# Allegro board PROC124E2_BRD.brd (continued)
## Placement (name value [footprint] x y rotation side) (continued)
R380  10K  [RES0201_0-5]  62.28 89.56 270 bottom
R381  2.2K  [RES0201_0-5]  61.52 89.56 90 bottom
R382  10K  [RES0201_0-5]  2.36 86.33 0 bottom
R383  0E  [RES0201_0-5]  54.28 88.78 0 bottom
R384  2.2K  [RES0402_0-5]  31.7 88.31 90 bottom
R385  0E  [RES0201_0-5]  64.27 88.3 180 bottom
R386  100K_1%  [RES0402_0-5]  64.42 86.83 270 bottom
R387  56.2K_1%  [RES0402_0-5]  26.64 86.36 90 bottom
R388  10E_1%  [RES0402_0-5]  20.85 85.25 0 bottom
R389  316K_1%  [RES0402_0-5]  64.42 84.8 90 bottom
R390  100K_1%  [RES0402_0-5]  63.15 84.8 270 bottom
R391  10E_1%  [RES0402_0-5]  20.85 83.98 0 bottom
R392  0E  [RES0201_0-5]  15.52 83.75 90 bottom
R393  0E  [RES0201_0-5]  78.14 83.55 0 bottom
R394  0E  [RES0201_0-5]  80.81 83.48 0 bottom
R395  220E  [RES0402_0-5]  82.33 82.87 270 bottom
R396  10E_1%  [RES0402_0-5]  23.79 80.01 180 bottom
R397  0E  [RES0201_0-5]  29.06 79.94 0 bottom
R398  49.9K_1%  [RES0201_0-5]  48.4 79.36 0 bottom
R399  10E_1%  [RES0402_0-5]  23.79 78.74 180 bottom
R400  49.9K_1%  [RES0201_0-5]  51.12 78.6 270 bottom
R401  49.9K_1%  [RES0201_0-5]  49.41 78.27 0 bottom
R402  1K_1%  [RES0201_0-5]  2.63 77.45 0 bottom
R403  0E  [RES0201_0-5]  19.29 76.95 180 bottom
R404  10K  [RES0201_0-5]  11.21 76.91 0 bottom
R405  0E  [RES0201_0-5]  18 76.67 270 bottom
R406  1K_1%  [RES0402_0-5]  8.25 73.89 90 bottom
R407  10K  [RES0201_0-5]  50.84 73.57 180 bottom
R408  10E_1%  [RES0402_0-5]  18.59 72.48 180 bottom
R409  0E  [RES0201_0-5]  24.09 72.34 0 bottom
R410  10E_1%  [RES0402_0-5]  18.59 71.21 180 bottom
R411  100K_1%  [RES0402_0-5]  44.06 71.03 180 bottom
R412  4.7K  [RES0201_0-5]  49.13 70.29 0 bottom
R413  10E_1%  [RES0402_0-5]  7.7 69.9 0 bottom
R414  0E  [RES0201_0-5]  2.44 69.07 90 bottom
R415  10E_1%  [RES0402_0-5]  7.7 68.63 0 bottom
R416  4.7K  [RES0201_0-5]  42.53 66.8 180 bottom
R417  0E  [RES0603_0-75]  79.67 65.19 270 bottom
R418  10K  [RES0201_0-5]  45.07 60.59 0 bottom
R419  4.7K  [RES0201_0-5]  39.99 60.59 180 bottom
R420  0E  [RES0201_0-5]  17.34 59.07 180 bottom
R421  0E  [RES0201_0-5]  15.43 59.07 0 bottom
R422  10K_1%  [RES0201_0-5]  70.2 58.05 180 bottom
R423  10K  [RES0201_0-5]  9 55.79 180 bottom
R424  4.7K  [RES0201_0-5]  7.27 54.32 270 bottom
R425  10K  [RES0201_0-5]  77.1 53.86 270 bottom
R426  10K  [RES0201_0-5]  76.19 53.86 270 bottom
R427  0E  [RES0201_0-5]  73.18 53.4 270 bottom
R428  0E  [RES0201_0-5]  80.43 53.27 270 bottom
R429  0E  [RES0201_0-5]  79.41 53.27 270 bottom
R430  0E  [RES0201_0-5]  71.66 53.26 90 bottom
R431  4.7K  [RES0201_0-5]  8.95 53.23 180 bottom
R432  2.2K  [RES0201_0-5]  19.09 53.18 0 bottom
R433  0E  [RES0201_0-5]  19.1 52.46 0 bottom
R434  0E  [RES0402_0-5]  67.04 51.45 90 bottom
R435  100K_1%  [RES0402_0-5]  16.12 51.45 180 bottom
R436  10K  [RES0201_0-5]  20.98 50.94 270 bottom
R437  1M_1%  [RES0402_0-5]  18.66 50.72 270 bottom
R438  10K  [RES0201_0-5]  24.21 50.54 270 bottom
R439  10K  [RES0201_0-5]  23.29 50.54 270 bottom
R440  100K_1%  [RES0402_0-5]  29.5 49.51 0 bottom
R441  32.4K_1%  [RES0402_0-5]  31.13 48.68 90 bottom
R442  100K  [RES0201_0-5]  32.15 48.51 270 bottom
R443  10K  [RES0201_0-5]  25.5 47.89 180 bottom
R444  1K_1%  [RES0402_0-5]  27.91 47.32 90 bottom
R445  100K_1%  [RES0402_0-5]  29.5 46.85 0 bottom
R446  0E  [RES0201_0-5]  25.5 46.68 180 bottom
R447  0E  [RES0201_0-5]  25.5 45.92 180 bottom
R448  100K_1%  [RES0402_0-5]  13.44 45.8 180 bottom
R449  0E  [RES0201_0-5]  15.22 45.69 180 bottom
R450  43.2K_1%  [RES0402_0-5]  29.5 45.58 180 bottom
R451  10K  [RES0201_0-5]  59.93 44.97 180 bottom
R452  10K_1%  [RES0201_0-5]  15.22 44.93 180 bottom
R453  0E  [RES0402_0-5]  25.81 44.74 0 bottom
R454  100K_1%  [RES0402_0-5]  13.44 44.53 180 bottom
R455  10K  [RES0201_0-5]  61.16 44.41 90 bottom
R456  10K  [RES0201_0-5]  59.93 44.21 0 bottom
R457  0E  [RES0402_0-5]  68.03 43.72 180 bottom
R458  2.2K_1%  [RES0201_0-5]  78.35 43.49 180 bottom
R459  0E  [RES0402_0-5]  25.81 43.47 0 bottom
R460  10K  [RES0201_0-5]  64.02 42.58 90 bottom
R461  0E  [RES0402_0-5]  25.81 42.2 0 bottom
R462  10K  [RES0201_0-5]  49.33 42.09 270 bottom
R463  10K  [RES0201_0-5]  49.62 41.07 180 bottom
R464  0E  [RES0402_0-5]  25.77 40.63 0 bottom
R465  0E  [RES0201_0-5]  21.45 40.04 0 bottom
R466  100K  [RES0201_0-5]  23.2 40.02 270 bottom
R467  0E  [RES0201_0-5]  50.26 39.23 0 bottom
R468  10K  [RES0201_0-5]  51.82 38.95 270 bottom
R469  10K  [RES0201_0-5]  62.11 38.82 90 bottom
R470  10K  [RES0201_0-5]  56.11 38.8 180 bottom
R471  10K  [RES0201_0-5]  57.29 38.04 180 bottom
R472  10K  [RES0201_0-5]  55.23 36.28 90 bottom
R473  4.7K  [RES0201_0-5]  62.71 35.25 270 bottom
R474  4.7K  [RES0201_0-5]  61.75 35.25 270 bottom
R475  1K_1%  [RES0201_0-5]  11.35 35.17 0 bottom
R476  1K_1%  [RES0201_0-5]  10.3 34.3 270 bottom
R477  10K_1%  [RES0201_0-5]  15.04 33.92 90 bottom
R478  100K_1%  [RES0402_0-5]  11.44 33.32 270 bottom
R479  4.7K  [RES0201_0-5]  62.74 33.16 270 bottom
R480  4.7K  [RES0201_0-5]  61.72 33.16 270 bottom
R481  0E  [RES0201_0-5]  22.73 33.02 0 bottom
R482  10K_1%  [RES0201_0-5]  15.01 32.59 270 bottom
R483  10K  [RES0201_0-5]  50.11 28.85 180 bottom
R484  10K_1%  [RES0201_0-5]  17.65 28.36 0 bottom
R485  10K  [RES0201_0-5]  80.53 27.83 90 bottom
R486  30K  [RES0402_0-5]  77.79 27.26 90 bottom
R487  51K  [RES0402_0-5]  76.52 27.26 270 bottom
R488  10K  [RES0201_0-5]  46.96 27.19 0 bottom
R489  10K  [RES0201_0-5]  42.15 27.15 180 bottom
R490  10K  [RES0201_0-5]  70.34 25.68 0 bottom
R491  1.1K_1%  [RES0201_0-5]  80.53 25.5 270 bottom
R492  10K  [RES0201_0-5]  70.34 24.92 180 bottom
R493  100E_1%  [RES0402_0-5]  56.54 24.69 180 bottom
R494  33E  [RES0201_0-5]  47.58 24.36 270 bottom
R495  10K  [RES0201_0-5]  44.46 24.01 90 bottom
R496  10K  [RES0201_0-5]  39.34 23.91 270 bottom
R497  10K  [RES0201_0-5]  66 23.89 90 bottom
R498  0E  [RES0201_0-5]  78.98 23.86 270 bottom
R499  10K  [RES0201_0-5]  14.37 23.81 90 bottom
R500  10K  [RES0201_0-5]  11.96 23.81 90 bottom
R501  10K  [RES0201_0-5]  11.2 23.81 90 bottom
R502  0E  [RES0201_0-5]  62.19 23.66 270 bottom
R503  0E  [RES0201_0-5]  61.43 23.66 270 bottom
R504  10K  [RES0201_0-5]  64.83 23.61 180 bottom
R505  4.7K  [RES0201_0-5]  37.83 23.53 180 bottom
R506  2.2K  [RES0201_0-5]  13.18 23.53 0 bottom
R507  1K_1%  [RES0402_0-5]  72.73 23.44 0 bottom
R508  22E_1%  [RES0201_0-5]  67.71 23.05 180 bottom
R509  10K  [RES0201_0-5]  65.28 22.54 0 bottom
R510  10K  [RES0201_0-5]  32.3 22.36 0 bottom
R511  1K_1%  [RES0402_0-5]  72.73 22.17 0 bottom
R512  100E_1%  [RES0402_0-5]  45.09 22.05 270 bottom
R513  10K  [RES0201_0-5]  32.3 21.47 180 bottom
R514  10K  [RES0201_0-5]  51.07 20.96 270 bottom
R515  1K_1%  [RES0402_0-5]  72.73 20.9 0 bottom
R516  4.7K  [RES0201_0-5]  32.61 20.28 90 bottom
R517  10K  [RES0201_0-5]  45.81 19.76 0 bottom
R518  1K_1%  [RES0402_0-5]  72.73 19.63 0 bottom
R519  4.7K  [RES0201_0-5]  51.38 19.51 0 bottom
R520  10K  [RES0201_0-5]  57.9 19.46 0 bottom
R521  10K  [RES0201_0-5]  45.81 18.84 180 bottom
R522  22E_1%  [RES0201_0-5]  51.35 18.68 180 bottom
R523  10K  [RES0201_0-5]  61.41 18.35 270 bottom
R524  10K  [RES0201_0-5]  59.23 18.35 270 bottom
R525  0E  [RES0201_0-5]  60.4 18.14 270 bottom
R526  0E  [RES0201_0-5]  58.21 18.14 270 bottom
R527  10K  [RES0201_0-5]  39.16 18.09 180 bottom
R528  4.7K  [RES0201_0-5]  24.85 18.02 270 bottom
R529  0E  [RES0201_0-5]  57.07 17.97 270 bottom
R530  10K  [RES0201_0-5]  45.92 17.92 180 bottom
R531  10K  [RES0201_0-5]  42.74 17.55 90 bottom
R532  10K  [RES0201_0-5]  35.88 17.55 90 bottom
R533  10K  [RES0201_0-5]  24.14 17.46 270 bottom
R534  10K  [RES0201_0-5]  23.25 17.46 90 bottom
R535  10K  [RES0201_0-5]  47.66 17.15 180 bottom
R536  0E  [RES0201_0-5]  70.01 17.02 0 bottom
R537  4.7K  [RES0201_0-5]  67.78 16.82 0 bottom
R538  10K  [RES0201_0-5]  31.57 16.7 270 bottom
R539  0E  [RES0805_0-75]  74.45 16.46 270 bottom
R540  0E  [RES0201_0-5]  55.83 16.14 270 bottom
R541  10K  [RES0201_0-5]  64.97 16.1 270 bottom
R542  10K  [RES0201_0-5]  62.78 16.1 270 bottom
R543  10K  [RES0201_0-5]  60.52 16.1 270 bottom
R544  0E  [RES0201_0-5]  54.56 16.02 270 bottom
R545  0E  [RES0201_0-5]  53.29 16.02 270 bottom
R546  0E  [RES0201_0-5]  51.46 16.02 270 bottom
R547  4.7K  [RES0201_0-5]  34.96 15.99 180 bottom
R548  12K_1%  [RES0402_0-5]  16.86 15.94 0 bottom
R549  0E  [RES0201_0-5]  63.95 15.89 270 bottom
R550  0E  [RES0201_0-5]  61.77 15.89 270 bottom
R551  0E  [RES0201_0-5]  59.51 15.89 270 bottom
R552  0E  [RES0201_0-5]  57.25 15.89 270 bottom
R553  0E  [RES0201_0-5]  67.43 15.57 0 bottom
R554  4.7K  [RES0201_0-5]  20.66 15.46 180 bottom
R555  4.7K  [RES0201_0-5]  66 15.29 90 bottom
R556  10K  [RES0201_0-5]  19.47 15.15 270 bottom
R557  10K  [RES0201_0-5]  18.59 15.15 90 bottom
R558  33E  [RES0201_0-5]  39.15 14.39 0 bottom
R559  100K_1%  [RES0402_0-5]  44.75 13.98 90 bottom
R560  10K  [RES0201_0-5]  35.24 11.49 0 bottom
R561  10K  [RES0201_0-5]  31.14 10.28 90 bottom
R562  10K  [RES0201_0-5]  35.24 10.22 0 bottom
R563  0E  [RES0201_0-5]  43.09 9.71 180 bottom
R564  10K  [RES0201_0-5]  32.04 9.43 270 bottom
R565  0E  [RES0402_0-5]  44.82 8.19 90 bottom
R566  4.7K  [RES0201_0-5]  31.81 7.83 90 bottom
R567  10K  [RES0201_0-5]  73.32 149.61 270 bottom
R568  10K  [RES0201_0-5]  72.5 144.94 0 bottom
R569  10K  [RES0201_0-5]  71.61 143.93 180 bottom
R570  10K  [RES0201_0-5]  70.11 142.73 180 bottom
R571  10K  [RES0201_0-5]  68.82 149.26 270 bottom
R572  10K  [RES0201_0-5]  69.58 149.26 270 bottom
R573  10K  [RES0201_0-5]  71.61 147.61 0 bottom
R574  10K  [RES0201_0-5]  71.61 146.85 180 bottom
R575  10K  [RES0201_0-5]  74.08 149.61 90 bottom
R576  10K  [RES0201_0-5]  74.84 149.61 270 bottom
R577  0E  [RES0201_0-5]  10.26 82.8 0 bottom
R578  10K  [RES0201_0-5]  12.32 71.42 0 bottom
R581  0E  [RES0201_0-5]  46.96 152.81 180 top
R582  0E  [RES0201_0-5]  46.96 151.08 180 top
R584  0E  [RES0201_0-5]  22.96 98.02 270 top
R585  0E  [RES0201_0-5]  21.77 98.02 90 top
R586  10K  [RES0201_0-5]  21.23 97.46 0 bottom
R587  0E  [RES0402_0-5]  21.95 100.56 0 bottom
R588  0E  [RES0201_0-5]  21.36 98.98 270 bottom
R589  100K_1%  [RES0402_0-5]  16.11 51.46 0 top
R590  0E  [RES0201_0-5]  17.81 77.8 180 bottom
R591  10K  [RES0201_0-5]  16.61 82.63 0 top
R592  1K_1%  [RES0201_0-5]  26.03 32.02 180 bottom
R593  10K  [RES0201_0-5]  23.27 28.71 270 bottom
R594  0E  [RES0201_0-5]  24.58 28.99 0 bottom
R595  8.2K_1%  [RES0201_0-5]  43 148.11 180 top
R627  22E_1%  [RES0201_0-5]  58.51 122.79 270 bottom
R628  22E_1%  [RES0201_0-5]  59.4 122.79 270 bottom
R629  0E  [RES0201_0-5]  74.74 128.41 0 bottom
R630  2.2K  [RES0201_0-5]  61.52 112.11 90 bottom
R631  2.49K_1%  [RES0402_0-5]  57.45 119.06 180 top
R632  0E  [RES0402_0-5]  55.1 118.07 0 bottom
R633  2.49K_1%  [RES0402_0-5]  62.76 120.82 0 top
R634  2.2K  [RES0201_0-5]  61.94 122.79 90 bottom
R635  2.49K_1%  [RES0402_0-5]  56.05 122.81 270 bottom
R636  11K_1%  [RES0402_0-5]  66.19 114.15 0 bottom
R637  2.49K_1%  [RES0402_0-5]  57.45 120.37 180 top
R638  2.49K_1%  [RES0402_0-5]  62.22 124.79 270 bottom
R639  0E  [RES0603_0-75]  72.83 126.21 180 bottom
R640  2.49K_1%  [RES0402_0-5]  55.1 120.71 180 bottom
R641  0E  [RES0201_0-5]  74.51 105.8 90 bottom
R642  2.49K_1%  [RES0402_0-5]  57.77 122.65 180 top
R643  2.49K_1%  [RES0402_0-5]  58.26 124.86 270 bottom
R644  0E  [RES0402_0-5]  63.29 111.4 90 bottom
R645  2.49K_1%  [RES0402_0-5]  57.77 124.37 180 top
R646  0E  [RES0402_0-5]  61.12 113.75 0 top
R647  220E  [RES0402_0-5]  77.75 126.97 0 bottom
R648  10K  [RES0201_0-5]  62.95 122.79 90 bottom
R649  2.49K_1%  [RES0402_0-5]  59.53 124.86 270 bottom
R650  2.49K_1%  [RES0402_0-5]  62.94 122.79 0 top
R651  0E  [RES0201_0-5]  69.33 106.16 90 bottom
R652  10K  [RES0201_0-5]  62.28 112.11 270 bottom
R653  11K_1%  [RES0402_0-5]  55.1 119.21 180 bottom
R654  5.76K_1%  [RES0402_0-5]  57.49 122.81 270 bottom
R655  220E  [RES0402_0-5]  72.99 106.72 90 bottom
R656  220E  [RES0402_0-5]  78.17 106.36 90 bottom
R657  10K  [RES0201_0-5]  58.33 104.41 270 bottom
R658  10K  [RES0201_0-5]  59.24 107.97 0 bottom
R659  10K  [RES0201_0-5]  59.24 107.21 0 bottom
R660  0E  [RES0201_0-5]  57.29 104.41 90 bottom
R661  10K  [RES0201_0-5]  60.22 104.29 270 bottom
RA1  0E  [RESA_EXB_0201-4_0-5]  38.85 122.25 0 top
RA2  0E  [RESA_EXB_0201-4_0-5]  31.65 118.68 180 top
RA3  0E  [RESA_EXB_0201-4_0-5]  34.09 118.66 180 top
RA4  0E  [RESA_EXB_0201-4_0-5]  38.85 119.84 0 bottom
RA5  1K  [RESA_EXB_0201-4_0-5]  38.52 115.48 270 bottom
RA6  1K  [RESA_EXB_0201-4_0-5]  38.52 113.58 270 bottom
RA7  1K  [RESA_EXB_0201-4_0-5]  39.33 55.74 270 bottom
RA8  1K  [RESA_EXB_0201-4_0-5]  29.35 52.49 180 bottom
SW1  7914G-1-000E  [SW4_100X216_200X200_SMD_4-2]  3 87.45 0 top
SW2  7914G-1-000E  [SW4_100X216_200X200_SMD_4-2]  81.15 58.19 180 top
SW3  416131160808  [SW16_416131160808_460X230_SMD_2-7]  36.56 31.46 180 top
SW4  416131160808  [SW16_416131160808_460X230_SMD_2-7]  50.03 31.46 180 top
SW5  7914G-1-000E  [SW4_100X216_200X200_SMD_4-2]  35.52 20.58 0 top
SW6  7914G-1-000E  [SW4_100X216_200X200_SMD_4-2]  42.38 20.58 0 top
TP1  -  [TP20_SMD]  49.61 152.13 0 top
TP2  -  [TP20_SMD]  67.08 151.88 0 top
TP3  -  [TP20_SMD]  49.34 148.45 0 top
TP4  -  [TP20_SMD]  48.02 148.04 0 top
TP5  -  [TP20_SMD]  49.21 147.12 0 top
TP6  -  [TP20_SMD]  48.43 145.98 0 top
TP7  -  [TP20_SMD]  49.85 145.73 0 top
TP8  -  [TP20_SMD]  49.32 144.56 0 top
TP9  -  [TP20_SMD]  77.78 140.29 0 top
TP10  -  [TP20_SMD]  79.82 140.29 0 top
TP11  -  [TP20_SMD]  70.91 136.35 0 top
TP12  -  [TP20_SMD]  80.32 134.96 0 top
TP13  -  [TP20_SMD]  78.47 133.74 0 top
TP14  -  [TP20_SMD]  12.69 125.77 270 top
TP15  -  [TP20_SMD]  10.97 125.44 270 bottom
TP16  -  [TP20_SMD]  12.68 119.99 270 top
TP17  -  [TP20_SMD]  11.99 118.38 270 bottom
TP18  -  [TP20_SMD]  18.12 109.83 0 top
TP20  -  [TP20_SMD]  21.9 105.16 90 top
TP21  -  [TP20_SMD]  21.45 104.17 180 top
TP22  -  [TP20_SMD]  14.63 102.51 0 top
TP23  -  [TP20_SMD]  58.89 103.25 0 top
TP24  -  [TP20_SMD]  60.48 102.27 0 top
TP25  -  [TP20_SMD]  15.72 102.82 0 top
TP26  -  [TP20_SMD]  59.32 102.1 0 top
TP27  -  [TP20_SMD]  64.4 100.64 0 top
TP28  -  [TP20_SMD]  64.36 98.09 0 top
TP29  -  [TP20_SMD]  65.07 99.49 0 top
TP30  -  [TP20_SMD]  35.8 92.67 0 top
TP31  -  [TP20_SMD]  11.78 94.01 270 top
TP32  -  [TP20_SMD]  4.19 91.87 0 top
TP33  -  [TP20_SMD]  25.11 91.82 270 top
TP34  -  [TP20_SMD]  65 90.38 0 top
TP35  -  [TP20_SMD]  56.3 90.17 180 top
TP36  -  [TP20_SMD]  24.04 89.1 0 top
TP37  -  [TP20_SMD]  64.66 89.09 0 top
TP38  -  [TP20_SMD]  58.45 88.74 0 top
TP39  -  [TP20_SMD]  12.22 86.29 0 top
TP40  -  [TP20_SMD]  65.41 85.25 90 top
TP41  -  [TP20_SMD]  9.86 83.98 270 top
TP42  -  [TP20_SMD]  16.23 85.22 0 top
TP43  -  [TP20_SMD]  43.21 83.47 0 top
TP44  -  [TP20_SMD]  21.03 81.75 270 top
TP45  -  [TP20_SMD]  7.62 79.67 270 top
TP46  -  [TP20_SMD]  6.6 77.72 0 top
TP47  -  [TP20_SMD]  7.54 75.84 0 top
TP48  -  [TP20_SMD]  10.09 76.08 0 top
TP49  -  [TP20_SMD]  18.6 75.39 0 top
TP50  -  [TP20_SMD]  9.67 74.91 0 top
TP51  -  [TP20_SMD]  12.02 74.33 0 top
TP52  -  [TP20_SMD]  13.08 74.33 0 top
TP53  -  [TP20_SMD]  14.56 74.31 270 top
TP54  -  [TP20_SMD]  49.16 56.52 0 top
TP55  -  [TP20_SMD]  72.49 54.25 180 top
TP56  -  [TP20_SMD]  41.31 53.7 90 top
TP57  -  [TP20_SMD]  73.11 53.38 180 top
TP58  -  [TP20_SMD]  77.69 51.9 180 top
TP59  -  [TP20_SMD]  78.8 51.9 180 top
TP60  -  [TP20_SMD]  72.16 51.74 180 top
TP61  -  [TP20_SMD]  73.16 51.74 180 top
TP62  THRU HOLE  [TP_40X65]  82.9 50.56 0 top
TP63  THRU HOLE  [TP_40X65]  82.9 48.02 0 top
TP64  -  [TP20_SMD]  78.77 46.63 180 top
TP65  -  [TP20_SMD]  79.69 46.63 180 top
TP66  -  [TP20_SMD]  62.73 45.49 0 top
TP67  THRU HOLE  [TP_40X65]  82.9 45.48 0 top
TP68  -  [TP20_SMD]  72.91 43.03 180 top
TP69  -  [TP20_SMD]  73.91 43.03 180 top
TP70  -  [TP20_SMD]  49.3 40.85 90 top
TP71  -  [TP20_SMD]  56.45 38.65 0 top
TP72  -  [TP20_SMD]  65.43 35.94 0 top
TP73  -  [TP20_SMD]  29.73 35.45 90 top
TP74  -  [TP20_SMD]  66.04 33.55 0 top
TP75  -  [TP20_SMD]  13.38 33.79 0 top
TP76  -  [TP20_SMD]  17.73 33.11 180 top
TP77  -  [TP20_SMD]  68.34 29.29 90 top
TP78  -  [TP20_SMD]  67.45 28.66 90 top
TP79  -  [TP20_SMD]  67.08 25.51 0 top
TP80  -  [TP20_SMD]  64.45 25.28 270 top
TP81  -  [TP20_SMD]  74.54 24.87 0 top
TP82  -  [TP20_SMD]  39.33 24.1 270 top
TP83  -  [TP20_SMD]  53.01 23.27 90 top
TP84  -  [TP20_SMD]  52.58 22.59 90 top
TP85  -  [TP20_SMD]  52.76 21.71 90 top
TP86  -  [TP20_SMD]  51.88 21.17 90 top
TP87  -  [TP20_SMD]  45.13 26.6 180 bottom
TP88  -  [TP20_SMD]  50.05 16.51 0 top
TP89  -  [TP20_SMD]  39.02 16.39 270 top
TP90  -  [TP20_SMD]  74.68 15.39 0 top
TP91  -  [TP20_SMD]  73.32 14.11 0 top
TP92  -  [TP20_SMD]  72.16 10.08 0 top
TP93  -  [TP20_SMD]  12.15 138.44 270 bottom
TP94  -  [TP20_SMD]  11.99 135.8 270 bottom
TP95  -  [TP20_SMD]  4.35 135.72 270 bottom
TP96  -  [TP20_SMD]  4.35 134.87 270 bottom
TP100  -  [TP20_SMD]  2.64 84.35 180 bottom
TP101  -  [TP20_SMD]  5.92 88.7 0 bottom
TP102  -  [TP20_SMD]  69.15 49.97 180 bottom
TP103  -  [TP20_SMD]  69.15 48.83 0 bottom
TP104  -  [TP20_SMD]  43.45 13.49 90 bottom
TP119  -  [TP20_SMD]  64.36 120.65 0 top
TP120  -  [TP20_SMD]  60.48 124.82 0 top
TP121  -  [TP20_SMD]  58.89 125.81 180 top
TP122  -  [TP20_SMD]  59.32 124.66 0 top
TP123  -  [TP20_SMD]  64.4 123.2 0 top
TP124  -  [TP20_SMD]  58.45 111.29 0 top
TP125  -  [TP20_SMD]  65.07 122.05 0 top
TP126  -  [TP20_SMD]  64.66 111.65 0 top
TP127  -  [TP20_SMD]  65 112.93 0 top
U1  32.768KHz  [OSC4_ECS-327MVATX-2_100X80_SMD_1]  44.24 151.87 180 top
U2  TXS0102DQER  [X2SON8_TXS0102_40X60_0-4]  41.5 149.07 0 top
U3  TCA6424ARGJR  [QFN32_19-68_200X200]  54.06 147.55 270 top
U4  TCA9543APWR  [TSSOP14_25-59_205X180_1-2]  43.58 141.58 270 top
U5  25.000MHz  [OSC4_ECS-2520MV_100X80_SMD_0-9]  51.81 138.47 90 top
U6  LMK1C1104PWR  [TSSOP8_25-59_125X180_1-2]  59.62 137.72 0 top
U7  TLV7103318DSET  [WSON6_19-68_60X60]  77.82 137.33 0 top
U8  SN74LVC1G08DBVRE4  [SOT23-5]  31.76 124.04 180 top
U9  12.288MHz  [OSC4_KC3225Z_130X100_SMD_0-8]  11.36 122.94 90 top
U10  W35N01JWTBAG  [TPBGA24_39-37_240X320_1-2]  44.66 121.9 180 top
U11  SiI9022ACNU  [QFN72_19-68_390X390_0-9]  18.66 120.33 180 top
U12  XAM6254ATGGHIAMC  [FCBGA441_31-49_680X680_2-6]  35.67 104.94 90 top
U13  TPS22918DBVR  [SOT23-6]  9.74 103.29 180 top
U14  TPD2E001DRLR  [SOT553-5_0-6]  2.73 99.63 180 top
U15  TPD6E001RSER  [UQFN10_19-68_80X60_0-6]  8.45 96.47 270 top
U16  INA231AIYFDR  [DSBGA12_15-74_60X70_0-4]  14.28 95.18 90 top
U17  INA231AIYFDR  [DSBGA12_15-74_60X70_0-4]  7.15 92.39 90 top
U18  TLV75518PDQNR  [X2SON4_TLV71318P_40X40_0-4]  26.22 90.47 0 top
U19  TXS0102DQER  [X2SON8_TXS0102_40X60_0-4]  24.31 87.46 270 top
U20  MT53E1G16D1FW-046 WT:A  [TFBGA200_MT53E1G16D1FW_400X570_1-1]  36.44 82.41 0 top
U21  MTFC16GAPALBH-IT  [VFBGA153_19-68_460X520_1-1]  50.88 81.11 0 top
U22  PTPS6521920WRHBRQ1  [QFN32_19-68_200X200_1_EP3-8]  13.07 79.54 270 top
U23  TPD3S014-Q1  [SOT23-6_1-5]  67.26 71.83 0 top
U24  TMP100NA/3K  [SOT23-6_1-5]  41.78 70.35 180 top
U25  SN74LVC1G08DBVRE4  [SOT23-5]  47.48 69.56 180 top
U26  SN74CB3Q3257PWR  [TSSOP16_25-59_205X180]  31.07 69.3 180 top
U27  SN74LVC3G17DCUR  [VSSOP8_19-68_85X95_0-9]  75.98 60.69 180 top
U28  M24512-DFMC6TG  [UFDFPN8_M24512_120X80_0-6]  8.51 56.96 270 top
U29  TPS22965DSGT  [WSON8_19-68_80X80_0-8]  45.74 54.61 0 top
U30  W25Q80DVSNIG  [SOIC8_1-8]  30.44 48.75 0 top
U31  SN74LVC1G11DRYR  [SON6_SN74LVC2G17_40X60_0-6]  63.7 42.75 0 top
U32  TCA9517DR  [SOIC8_1-8]  62.23 33.34 90 top
U33  TPS630702RNMR  [VQFNHR15_TPS630701_100X120_1]  23.96 32.34 270 top
U34  SN74LVC1G08DBVRE4  [SOT23-5]  70.88 27.31 0 top
U35  TPD2E001DRLR  [SOT553-5_0-6]  8.57 16.57 90 top
U36  TM4C1294NCPDTT3R  [TQFP128_15-74_550X550_1-2]  62.17 16.03 90 top
U37  FT4232HL  [LQFP64_19-68_390X390_1-6]  22.57 14.46 0 top
U38  LM4040B25IDCKR  [SC70-5_1-1]  73.87 7.53 0 top
U39  SN74CB3Q3257PWR  [TSSOP16_25-59_205X180]  43.58 141.58 90 bottom
U40  TXB0104RUTR  [UQFN12_TXB0104RUT_70X80_0-6]  48.36 141.26 180 bottom
U41  SN74LVC1G04DPWR  [X2SON5_TLV7021_30X30_0-4]  34.11 139.38 180 bottom
U42  SN74CB3Q3257PWR  [TSSOP16_25-59_205X180]  78.54 137.46 270 bottom
U43  SN74CB3Q3257PWR  [TSSOP16_25-59_205X180]  57.75 137.25 0 bottom
U44  SN74AVC4T245RSVR  [UQFN16_TMUX1574_70X100_0-6]  36.53 137.2 270 bottom
U45  TPS22946YZPR  [DSBGA6_19-68_40X60_0-5]  6.31 136.94 0 bottom
U46  TPS22902YFPR  [DSBGA4_15-74_30X30_0-5]  19.24 133.77 90 bottom
U47  SN74LVC1G08DBVRE4  [SOT23-5]  70.97 131.57 0 bottom
U48  TMP100NA/3K  [SOT23-6_1-5]  29.85 124.8 180 bottom
U50  TPD12S016PWR  [TSSOP24_25-59_315X180_1-2]  5.85 114.29 0 bottom
U52  SN74LVC1G11DRYR  [SON6_SN74LVC2G17_40X60_0-6]  15.94 110.91 180 bottom
U55  DP83867IRRGZ  [QFN48_19-68_280X280_1]  60.9 94.89 180 bottom
U56  TLV75510PDQNR  [X2SON4_TLV71318P_40X40_0-4]  54.99 90.08 180 bottom
U57  TPS62824DMQR  [VSONHR6_TPS62826_60X60_1]  62.31 86.96 180 bottom
U58  INA231AIYFDR  [DSBGA12_15-74_60X70_0-4]  17.43 84.63 270 bottom
U59  SN74LVC1G11DRYR  [SON6_SN74LVC2G17_40X60_0-6]  4.35 86.09 90 bottom
U60  INA231AIYFDR  [DSBGA12_15-74_60X70_0-4]  27.19 79.41 90 bottom
U61  INA231AIYFDR  [DSBGA12_15-74_60X70_0-4]  22.25 71.93 90 bottom
U62  SN74LVC1G08DBVRE4  [SOT23-5]  51.75 71.26 180 bottom
U63  INA231AIYFDR  [DSBGA12_15-74_60X70_0-4]  4.19 69.3 270 bottom
U64  12.288MHz  [OSC4_KC3225Z_130X100_SMD_0-8]  71.02 55.68 0 bottom
U65  TPS22902YFPR  [DSBGA4_15-74_30X30_0-5]  14.18 51.65 180 bottom
U66  TLV320AIC3106IRGZT  [VQFN48_19-68_285X285]  74.41 48.04 180 bottom
U67  LM61460AANQRJRRQ1  [VQFNHR14_LM61460_160X140_1]  33.72 45.22 0 bottom
U68  TPS65988DHRSHR  [VQFN56_TPS65987D_280X280_1]  20.38 45.16 0 bottom
U69  TVS2200DRVR  [SON6_25-59_85X85_0-8]  9.36 44.83 180 bottom
U70  TCA6424ARGJR  [QFN32_19-68_200X200]  54.45 42.86 0 bottom
U71  SN74LVC1G08DBVRE4  [SOT23-5]  61.16 41.63 270 bottom
U72  SN74LVC1G11DRYR  [SON6_SN74LVC2G17_40X60_0-6]  56.71 36.49 0 bottom
U73  SN74AVC8T245RHL  [QFN24_19-68_220X140_1]  54.47 31.4 90 bottom
U74  TCA6424ARGJR  [QFN32_19-68_200X200]  45.38 30.74 0 bottom
U75  SN74AVC8T245RHL  [QFN24_19-68_220X140_1]  37.86 30.74 270 bottom
U76  SN74LVC1G04DPWR  [X2SON5_TLV7021_30X30_0-4]  71.03 27.27 90 bottom
U77  TVS2200DRVR  [SON6_25-59_85X85_0-8]  10.26 26.15 90 bottom
U78  TPS79601DRBR  [SON8_25-59_130X130_1]  76.34 24.24 0 bottom
U79  TXS0102DQER  [X2SON8_TXS0102_40X60_0-4]  49.16 24.05 90 bottom
U80  SN74LVC1G32DPWR  [X2SON5_TLV7021_30X30_0-4]  46.02 23.97 0 bottom
U81  SN74LVC3G17DCUR  [VSSOP8_19-68_85X95_0-9]  39.24 20.88 90 bottom
U82  SN74AVC2T244DQMR  [X2SON8_15-74_70X50]  58.18 20.87 0 bottom
U83  SN74AVC4T245RSVR  [UQFN16_TMUX1574_70X100_0-6]  29.81 20.43 270 bottom
U84  SN74AVC4T245RSVR  [UQFN16_TMUX1574_70X100_0-6]  66.94 20.33 0 bottom
U85  TXS0102DQER  [X2SON8_TXS0102_40X60_0-4]  62.98 19.8 270 bottom
U86  93LC46B  [MSOP8_25-59_125X125_1-1]  12.29 19.66 270 bottom
U87  SN74AVC4T245RSVR  [UQFN16_TMUX1574_70X100_0-6]  48.86 19.29 270 bottom
U88  TPD4E004DRYR  [SON6_19-68_40X60_PB_0-6]  76.47 16.18 0 bottom
U89  SN74LVC1G11DRYR  [SON6_SN74LVC2G17_40X60_0-6]  33.01 16.09 90 bottom
U90  SN74LVC1G32DPWR  [X2SON5_TLV7021_30X30_0-4]  39.82 15.73 180 bottom
U91  SN74AVC4T245RSVR  [UQFN16_TMUX1574_70X100_0-6]  25.44 14.97 0 bottom
U92  SN74AVC4T245RSVR  [UQFN16_TMUX1574_70X100_0-6]  20.51 12.66 0 bottom
U93  TPS62177DQCR  [WSON10_19-68_80X120_0-8]  45.78 11.31 90 bottom
U94  TPS73533DRVR  [SON6_25-59_85X85]  10.51 10.09 180 bottom
U95  SN74AVC2T244DQMR  [X2SON8_15-74_70X50]  40.93 8.9 90 bottom
U96  SN74AVC4T245RSVR  [UQFN16_TMUX1574_70X100_0-6]  29.12 8.26 270 bottom
U97  TCA9406DCUR  [VSSOP8_19-68_85X95]  74.79 146.21 90 bottom
U98  TXB0108RGYR  [QFN20_19-68_185X145_1]  67.68 145.83 0 bottom
U125  TLV705075YFPT  [DSBGA4_15-74_30X30_0-5]  19.99 99.01 270 bottom
U127  DP83867IRRGZ  [QFN48_19-68_280X280_1]  60.9 117.45 180 bottom
U128  SN74LVC1G11DRYR  [SON6_SN74LVC2G17_40X60_0-6]  59.55 105.91 270 bottom
Y1  25.000MHz  [XTAL4_XRCGB-FM_80X60_SMD_0-7]  19 100.57 90 top
Y2  32.768KHz  [XTAL_ECS-32_130X60_SMD_0-9]  20.73 94.74 90 top
Y3  16.000MHz  [XTAL4_XRCGB-FM_80X60_SMD_0-7]  58.92 27.3 0 top
Y4  12.000MHz  [XTAL_ABM3_205X130_SMD_1-4]  12.32 17.46 270 top

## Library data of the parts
C1-C19 C25-C28 C31-C198 C201-C206 C208 C209 C212-C215 C217 C219-C223 C225-C227 C230 C232 C234-C242 C244 C246-C249 C252-C275 C277-C279 C281 C282 C284-C374 C376-C480 C507 C531 C533-C535 C562-C588 = CAP
C375 C532 = CAP_POL
D1 D4 D8 D9 D12 D13 = DIODE_SOD323
D2 D3 = DIODE_ZENER_SOT23_13
D5 D6 D10 D11 = DIODE_TVS_DUAL
D7 = DIODE_ESD122DMXR
FB1-FB3 = INDUCTOR_FERRITE
FL1 FL3 FL4 FL6 FL8-FL12 FL14-FL20 FL22 = EMIFILTER_IND
J1 = CON_PMC_20X2_F_DP_TI
J2 = CON_PCI_75_2199119-4_2230
J3 = HEADER_20X2
J5 = CON_HDMI_19X1
J7 J27 = CON_RJ45-14_LPJG16314A4NL
J8 J12 J16 = HEADER_2X1
J9 = CON_USB-A_4_2SH
J10 = HEADER_14x2
J11 = HEADER_10X2
J13 J15 = CON_USB-C_24_1240183621
J14 = CON_AUDIOJACK4_SJ-43514-SMT
J17 J18 = CON_USB_MINI-B
J19 = HEADER_10X2_FTR-06
J21 = CON_SDCARD9_MEM2075-00-140
J22 = CON_FLEX_40X1_SH4
J23 = HEADER_5X2
J24 = CON_FLEX_40X1_FH12A-40S-0.5SH
L1-L3 L6 L8-L10 = INDUCTOR
L4 L5 = INDUCTOR_DLW31S
LD3 LD5-LD12 = DIODE_LED
Q1 Q3 Q5-Q7 Q9 Q14 Q15 Q19-Q21 = MOSFET_CSD17313Q2
Q4 Q12 Q13 = MOSFET_IRLML6401TR
Q8 = NPN_BEC
Q10 Q11 = MOSFET_CSD25310Q2
R1-R35 R37 R39 R41 R47-R49 R51-R53 R55 R56 R59-R61 R63-R71 R73-R96 R98 R100 R102-R105 R107-R120 R122-R128 R130-R132 R137-R168 R170-R203 R206-R264 R278-R281 R286 R288-R305 R307 R309 R310 R317-R326 R332-R334 R338 R339 R342 R345 R348 R352 R354 R356 R359 R361-R376 R378-R578 R581 R582 R584-R595 R627-R631 R633-R661 = RESISTOR
R40 R273-R277 R329 R346 = RESISTOR: signal model: RESISTOR_RES0201_0-5_0E_0E
R43 R316 R377 R632 = RESISTOR: signal model: RESISTOR_RES0402_0-5_0E_0E
R101 R106 R121 R129 R134 R136 = RESISTOR-4TERM
R272 = RESISTOR: signal model: RESISTOR_RES0201_0-5_49.9K_1%_49.9K_1%
R282-R285 R287 = RESISTOR: signal model: RESISTOR_RES0201_0-5_10K_1%_10K_1%
R308 = RESISTOR: signal model: RESISTOR_RES0201_0-5_22E_1%_22E_1%
RA1 RA4-RA8 = RESARR_ISO4
RA2 RA3 = RESARR_ISO4: signal model: RESARR_ISO4_RESA_EXB_0201-4_0-5_0E
SW1 SW2 SW5 SW6 = 7914G-1-000E _7914G
SW3 SW4 = SW16_CHS-08A
TP1-TP18 TP20-TP96 TP100-TP104 TP119-TP127 = TESTPOINT
U1 U5 = OSC4_ASFL3
U2 U19 U79 U85 = TXS0102DQX_SON8
U3 U70 U74 = TCA6424ARGJR_QFN32
U4 = TCA9543APWR_TSSOP14
U6 = LMK1C1104_TSSOP8
U7 = TLV7103318D_WSON6
U8 U25 U34 U47 U62 U71 = SN74LVC1G08DBVRE4_SOT23-5
U9 U64 = OSC_KC2016K
U10 = W35N01JWTB_TFBGA24
U11 = SII9022ACNU_QFN72
U12 = AM62Q_SoC_FCBGA441
U13 = TPS22918DBVR_SOT23-6
U14 U35 = TPD2E001DRLR_SOT-5
U15 = TPD6E001RSE_UQFN10
U16 U17 U58 U60 U61 U63 = INA231_DSBGA12
U18 U56 = TLV71318PDQNR_X2SON4
U20 = MT53E1G16D1FW_TFBGA200
U21 = MTFC16GAPALBH_TFBGA153
U22 = TPS65219_QFN32
U23 = TPD3S014D_SOT23-6
U24 U48 = TMP100NA/3K_SOT23-6
U26 U39 U42 U43 = SN74CB3Q3257PWR_TSSOP16
U27 U81 = SN74LVC3G17DCUR_VSSOP8
U28 = M24512_UFDFPN8
U29 = TPS22965DSGT_WSON8
U30 = W25Q80BWSNIG_SOIC8
U31 U52 U59 U72 U89 U128 = SN74LVC1G11DCKR_SC70-6
U32 = TCA9517DGKR_VSSOP8
U33 = TPS630701_VQFN-HR15
U36 = TM4C1294NCPDTT3R_TQFP128
U37 = FT4232H_LQFP64
U38 = LM4040B25IDCKR_SC70-5
U40 = TXB0104RUTR_UQFN12
U41 U76 = SN74LVC1G04DCKR_SC70-5
U44 U83 U84 U87 U91 U92 U96 = SN74AVC4T245RSV_UQFN16
U45 = TPS22946_DSBGA6
U46 U65 = TPS22912CYZVR_DSBGA4
U50 = TPD12S016PW_TSSOP24
U55 U127 = DP83867IRRGZ_VQFN48
U57 = TPS62827DMQR_VSONHR6
U66 = TLV320AIC3106IRGZT_VQFN48
U67 = LM61460_VQFNHR14
U68 = TPS65988DJ_VQFN56
U69 U77 = TVS2200_WSON6
U73 U75 = SN74AVC8T245RHL_QFN24
U78 = TPS79601DRBR_SON8
U80 U90 = SN74LVC1G32_X2SON5
U82 U95 = SN74AVC2T244DQMR_X2SON8
U86 = 93LC46B_MSOP8
U88 = TPD4E004_SON6
U93 = TPS62177_WSON10
U94 = TPS73501DRVR_SON6
U97 = TCA9406DCUR_VSSOP8
U98 = TXB0108RGYR_VQFN20
U125 = TLV7050_DSBGA4
Y1 Y3 = CRY4_13
Y2 Y4 = CRY

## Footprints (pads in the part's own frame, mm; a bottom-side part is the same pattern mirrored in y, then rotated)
CAP0201_0-5
  rect 0.356x0.33 smd: 1(-0.28,0) 2(0.28,0)
CAP0402_0-75
  rect 0.559x0.635 smd: 1(-0.49,0) 2(0.49,0)
CAP0603_1
  rect 0.94x1.016 smd: 1(-0.8,0) 2(0.8,0)
CAP0805_1-5
  rect 0.94x1.346 smd: 1(-0.8,0) 2(0.8,0)
CAP1206_1-75
  rect 1.143x1.803 smd: 1(-1.5,0) 2(1.5,0)
CAP1206_2
  rect 1.143x1.803 smd: 1(-1.5,0) 2(1.5,0)
CAP1210_2-75
  rect 0.94x2.591 smd: 1(-1.4,0) 2(1.4,0)
CAPT7343D_3-25
  rect 2.362x2.438 smd: 1(-3.1,0) 2(3.1,0)
CAPT7343X_4-3
  rect 2.743x2.54 smd: 1(-3.2,0) 2(3.2,0)
CON_19X1_10029449-001RLF_S_R_S_6-3
  rect 0.33x1.956 smd: 1(4.75,4.928) 2(4.25,4.928) 3(3.75,4.928) 4(3.25,4.928) 5(2.75,4.928) 6(2.25,4.928) 7(1.75,4.928) 8(1.25,4.928) 9(0.75,4.928) 10(0.25,4.928) 11(-0.25,4.928) 12(-0.75,4.928) 13(-1.25,4.928) 14(-1.75,4.928) 15(-2.25,4.928) 16(-2.75,4.928) 17(-3.25,4.928) 18(-3.75,4.928) 19(-4.25,4.928)
  round 2.007 hole 1.321: 20(7.25,3.928) 21(-7.25,3.928) 22(7.85,-0.972) 23(-7.85,-0.972)
CON_AV4_SJ-43514-SMT_S_R_S_5-1
  round 1.549 hole 1.676 unplated: (0,4.515) (0,-2.485)
  rect 2.819x2.007 smd: 1(3.7,-6.385)
  rect 2.819x2.819 smd: 2(3.7,5.815)
  rect 2.819x2.21 smd: 3(-3.7,-1.685) 4(3.7,-3.585)
CON_FLEX1X40_FFC2A32-40-T_S_S_S_4-3
  rect 0.61x1.499 smd: 1(-9.75,-1.4) 2(-9.25,1.4) 3(-8.75,-1.4) 4(-8.25,1.4) 5(-7.75,-1.4) 6(-7.25,1.4) 7(-6.75,-1.4) 8(-6.25,1.4) 9(-5.75,-1.4) 10(-5.25,1.4) 11(-4.75,-1.4) 12(-4.25,1.4) 13(-3.75,-1.4) 14(-3.25,1.4) 15(-2.75,-1.4) 16(-2.25,1.4) 17(-1.75,-1.4) 18(-1.25,1.4) 19(-0.75,-1.4) 20(-0.25,1.4) 21(0.25,-1.4) 22(0.75,1.4) 23(1.25,-1.4) 24(1.75,1.4) 25(2.25,-1.4) 26(2.75,1.4) 27(3.25,-1.4) 28(3.75,1.4) 29(4.25,-1.4) 30(4.75,1.4) 31(5.25,-1.4) 32(5.75,1.4) 33(6.25,-1.4) 34(6.75,1.4) 35(7.25,-1.4) 36(7.75,1.4) 37(8.25,-1.4) 38(8.75,1.4) 39(9.25,-1.4) 40(9.75,1.4)
  rect 0.787x1.499 smd: SH1(-10.75,-1.4) SH2(-10.75,1.4) SH3(10.75,-1.4) SH4(10.75,1.4)
CON_FLEX40X1_FH12A_S_R_S
  rect 0.33x1.397 smd: 1(-9.75,3.575) 2(-9.25,3.575) 3(-8.75,3.575) 4(-8.25,3.575) 5(-7.75,3.575) 6(-7.25,3.575) 7(-6.75,3.575) 8(-6.25,3.575) 9(-5.75,3.575) 10(-5.25,3.575) 11(-4.75,3.575) 12(-4.25,3.575) 13(-3.75,3.575) 14(-3.25,3.575) 15(-2.75,3.575) 16(-2.25,3.575) 17(-1.75,3.575) 18(-1.25,3.575) 19(-0.75,3.575) 20(-0.25,3.575) 21(0.25,3.575) 22(0.75,3.575) 23(1.25,3.575) 24(1.75,3.575) 25(2.25,3.575) 26(2.75,3.575) 27(3.25,3.575) 28(3.75,3.575) 29(4.25,3.575) 30(4.75,3.575) 31(5.25,3.575) 32(5.75,3.575) 33(6.25,3.575) 34(6.75,3.575) 35(7.25,3.575) 36(7.75,3.575) 37(8.25,3.575) 38(8.75,3.575) 39(9.25,3.575) 40(9.75,3.575)
  rect 1.803x2.311 smd: 41(-11.65,0.325) 42(11.65,0.325)
CON_MINIPCI75_2199119-4_S_R_S_3-2_2230
  round 0.991 hole 1.118 unplated: (-10,-1.437)
  round 1.448 hole 1.575 unplated: (10,-1.437)
  rect 0.305x1.575 smd: 1(-9.25,3.838) 2(-9,-3.712) 3(-8.75,3.838) 4(-8.5,-3.712) 5(-8.25,3.838) 6(-8,-3.712) 7(-7.75,3.838) 8(-7.5,-3.712) 9(-7.25,3.838) 10(-7,-3.712) 11(-6.75,3.838) 12(-6.5,-3.712) 13(-6.25,3.838) 14(-6,-3.712) 15(-5.75,3.838) 16(-5.5,-3.712) 17(-5.25,3.838) 18(-5,-3.712) 19(-4.75,3.838) 20(-4.5,-3.712) 21(-4.25,3.838) 22(-4,-3.712) 23(-3.75,3.838) 32(-1.5,-3.712) 33(-1.25,3.838) 34(-1,-3.712) 35(-0.75,3.838) 36(-0.5,-3.712) 37(-0.25,3.838) 38(0,-3.712) 39(0.25,3.838) 40(0.5,-3.712) 41(0.75,3.838) 42(1,-3.712) 43(1.25,3.838) 44(1.5,-3.712) 45(1.75,3.838) 46(2,-3.712) 47(2.25,3.838) 48(2.5,-3.712) 49(2.75,3.838) 50(3,-3.712) 51(3.25,3.838) 52(3.5,-3.712) 53(3.75,3.838) 54(4,-3.712) 55(4.25,3.838) 56(4.5,-3.712) 57(4.75,3.838) 58(5,-3.712) 59(5.25,3.838) 60(5.5,-3.712) 61(5.75,3.838) 62(6,-3.712) 63(6.25,3.838) 64(6.5,-3.712) 65(6.75,3.838) 66(7,-3.712) 67(7.25,3.838) 68(7.5,-3.712) 69(7.75,3.838) 70(8,-3.712) 71(8.25,3.838) 72(8.5,-3.712) 73(8.75,3.838) 74(9,-3.712) 75(9.25,3.838)
  rect 1.219x2.769 smd: SH1(-10.35,3.063) SH2(10.35,3.063)
  round 5.309 hole 2.997: SH3(0,-30)
CON_MUSBB5_629105150521_S_R_S_2-7
  round 0.686 hole 0.813 unplated: (-2.5,1.848) (2.5,1.848)
  rect 0.457x1.295 smd: 1(-1.3,2.948) 2(-0.65,2.948) 3(0,2.948) 4(0.65,2.948) 5(1.3,2.948)
  oval 1.448x2.311 hole 0.864x1.727: 6(-3.725,2.898) 7(3.725,2.898)
  oval 1.143x1.803 hole 0.559x1.219: 8(-3.875,-0.902) 9(3.875,-0.902)
CON_PMC2X20_QSH-020-01-D-DP-A_S_S_S_3-4
  round 0.889 hole 1.016 unplated: (-10.067,2.67) (10.067,2.67)
  rect 0.279x2.261 smd: 1(-7.257,-2.87) 2(-7.257,2.87) 3(-6.756,-2.87) 4(-6.756,2.87) 5(-5.756,-2.87) 6(-5.756,2.87) 7(-5.257,-2.87) 8(-5.257,2.87) 9(-4.257,-2.87) 10(-4.257,2.87) 11(-3.756,-2.87) 12(-3.756,2.87) 13(-2.756,-2.87) 14(-2.756,2.87) 15(-2.257,-2.87) 16(-2.257,2.87) 17(-1.257,-2.87) 18(-1.257,2.87) 19(-0.756,-2.87) 20(-0.756,2.87) 21(0.244,-2.87) 22(0.244,2.87) 23(0.743,-2.87) 24(0.743,2.87) 25(1.743,-2.87) 26(1.743,2.87) 27(2.244,-2.87) 28(2.244,2.87) 29(3.244,-2.87) 30(3.244,2.87) 31(3.743,-2.87) 32(3.743,2.87) 33(4.743,-2.87) 34(4.743,2.87) 35(5.244,-2.87) 36(5.244,2.87) 37(6.244,-2.87) 38(6.244,2.87) 39(6.743,-2.87) 40(6.743,2.87)
  rect 2.54x0.432 smd: SH1(-8.065,0) SH4(8.065,0)
  rect 4.699x0.432 smd: SH2(-3.175,0) SH3(3.175,0)
CON_RJ45-14_LPJG16314A4NL_S_R_T_13-6
  round 3.073 hole 3.2 unplated: (0,-8.89) (11.43,-8.89)
  rect 1.6x1.6 hole 0.914: 1(0,0)
  round 1.6 hole 0.914: 2(1.27,-2.54) 3(2.54,0) 4(3.81,-2.54) 5(5.08,0) 6(6.35,-2.54) 7(7.62,0) 8(8.89,-2.54) 9(10.16,0) 10(11.43,-2.54)
  round 1.702 hole 1.016: 11(12.44,-11.43) 12(12.44,-13.462) 13(-1.01,-11.43) 14(-1.01,-13.462)
  round 2.362 hole 1.676: 15(-2.032,-5.842) 16(13.462,-5.842)
CON_SD9_MEM2051-00-195-00_S_R_S_2-1
  rect 0.787x1.499 smd: 1(1.94,-3.66) 2(0.84,-3.26) 3(-0.26,-3.66) 4(-1.36,-3.86) 5(-2.46,-3.66) 6(-3.56,-3.86) 7(-4.66,-3.66) 8(-5.76,-3.66)
  rect 0.991x0.94 smd: 9(-3.56,7.425)
  rect 1.397x1.905 smd: SH1(6.6,-6.95) SH2(-6.55,-5.95)
  rect 1.295x1.397 smd: SH3(0.75,7.2) SH4(-4.95,7.2)
CON_USBA4_629104151_S_R_S_7-4
  round 1.092 hole 1.219 unplated: (-2.5,2.965) (2.5,2.965)
  rect 1.194x3.2 smd: 1(-3.5,6.665) 2(-1,6.665) 3(1,6.665) 4(3.5,6.665)
  oval 1.397x3.708 hole 0.711x2.997: SH1(-6.4,3.465) SH2(6.4,3.465)
CON_USBC24_2012670_S_R_S_3-9
  rect 0.305x0.762 smd: A1(-3,4.056) A2(-2.5,4.056) A3(-2,4.056) A4(-1.5,4.056) A5(-1,4.056) A6(-0.5,4.056) A7(0.5,4.056) A8(1,4.056) A9(1.5,4.056) A10(2,4.056) A11(2.5,4.056) A12(3,4.056) B2(2.25,2.356) B3(1.75,2.356) B4(1.25,2.356) B5(0.75,2.356) B6(0.25,2.356) B7(-0.25,2.356) B8(-0.75,2.356) B9(-1.25,2.356) B10(-1.75,2.356) B11(-2.25,2.356)
  rect 0.94x0.762 smd: B1(3.05,2.356) B12(-3.05,2.356)
  oval 1.194x2.21 hole 0.61x1.575: SH1(-4.32,3.246) SH2(4.32,3.246)
  oval 1.194x3.708 hole 0.61x2.083: SH3(4.62,-2.114) SH4(-4.62,-2.114)
DIO_DFN0201_0-4
  rect 0.229x0.381 smd: 1(-0.22,0) 2(0.22,0)
DIO_DFN0402_0-5
  rect 0.356x0.61 smd: 1(-0.34,0) 2(0.34,0)
DSBGA4_15-74_30X30_0-5
  round 0.279 smd: A1(-0.2,0.2) A2(0.2,0.2) B1(-0.2,-0.2) B2(0.2,-0.2)
DSBGA6_19-68_40X60_0-5
  round 0.33 smd: A1(-0.25,0.5) A2(0.25,0.5) B1(-0.25,0) B2(0.25,0) C1(-0.25,-0.5) C2(0.25,-0.5)
DSBGA12_15-74_60X70_0-4
  round 0.279 smd: A1(-0.4,0.6) A2(0,0.6) A3(0.4,0.6) B1(-0.4,0.2) B2(0,0.2) B3(0.4,0.2) C1(-0.4,-0.2) C2(0,-0.2) C3(0.4,-0.2) D1(-0.4,-0.6) D2(0,-0.6) D3(0.4,-0.6)
EMIFIL_BLM15A_0402_0-6
  rect 0.61x0.61 smd: 1(-0.46,0) 2(0.46,0)
FCBGA441_31-49_680X680_2-6
  round 0.406 smd: A1(-8,8) A2(-7.2,8) A3(-6.4,8) A4(-5.6,8) A5(-4.8,8) A6(-4,8) A7(-3.2,8) A8(-2.4,8) A9(-1.6,8) A10(-0.8,8) A11(0,8) A12(0.8,8) A13(1.6,8) A14(2.4,8) A15(3.2,8) A16(4,8) A17(4.8,8) A18(5.6,8) A19(6.4,8) A20(7.2,8) A21(8,8) AA1(-8,-8) AA2(-7.2,-8) AA3(-6.4,-8) AA4(-5.6,-8) AA5(-4.8,-8) AA6(-4,-8) AA7(-3.2,-8) AA8(-2.4,-8) AA9(-1.6,-8) AA10(-0.8,-8) AA11(0,-8) AA12(0.8,-8) AA13(1.6,-8) AA14(2.4,-8) AA15(3.2,-8) AA16(4,-8) AA17(4.8,-8) AA18(5.6,-8) AA19(6.4,-8) AA20(7.2,-8) AA21(8,-8) B1(-8,7.2) B2(-7.2,7.2) B3(-6.4,7.2) B4(-5.6,7.2) B5(-4.8,7.2) B6(-4,7.2) B7(-3.2,7.2) B8(-2.4,7.2) B9(-1.6,7.2) B10(-0.8,7.2) B11(0,7.2) B12(0.8,7.2) B13(1.6,7.2) B14(2.4,7.2) B15(3.2,7.2) B16(4,7.2) B17(4.8,7.2) B18(5.6,7.2) B19(6.4,7.2) B20(7.2,7.2) B21(8,7.2) C1(-8,6.4) C2(-7.2,6.4) C3(-6.4,6.4) C4(-5.6,6.4) C5(-4.8,6.4) C6(-4,6.4) C7(-3.2,6.4) C8(-2.4,6.4) C9(-1.6,6.4) C10(-0.8,6.4) C11(0,6.4) C12(0.8,6.4) C13(1.6,6.4) C14(2.4,6.4) C15(3.2,6.4) C16(4,6.4) C17(4.8,6.4) C18(5.6,6.4) C19(6.4,6.4) C20(7.2,6.4) C21(8,6.4) D1(-8,5.6) D2(-7.2,5.6) D3(-6.4,5.6) D4(-5.6,5.6) D5(-4.8,5.6) D6(-4,5.6) D7(-3.2,5.6) D8(-2.4,5.6) D9(-1.6,5.6) D10(-0.8,5.6) D11(0,5.6) D12(0.8,5.6) D13(1.6,5.6) D14(2.4,5.6) D15(3.2,5.6) D16(4,5.6) D17(4.8,5.6) D18(5.6,5.6) D19(6.4,5.6) D20(7.2,5.6) D21(8,5.6) E1(-8,4.8) E2(-7.2,4.8) E3(-6.4,4.8) E4(-5.6,4.8) E5(-4.8,4.8) E6(-4,4.8) E7(-3.2,4.8) E8(-2.4,4.8) E9(-1.6,4.8) E10(-0.8,4.8) E11(0,4.8) E12(0.8,4.8) E13(1.6,4.8) E14(2.4,4.8) E15(3.2,4.8) E16(4,4.8) E17(4.8,4.8) E18(5.6,4.8) E19(6.4,4.8) E20(7.2,4.8) E21(8,4.8) F1(-8,4) F2(-7.2,4) F3(-6.4,4) F4(-5.6,4) F5(-4.8,4) F6(-4,4) F7(-3.2,4) F8(-2.4,4) F9(-1.6,4) F10(-0.8,4) F11(0,4) F12(0.8,4) F13(1.6,4) F14(2.4,4) F15(3.2,4) F16(4,4) F17(4.8,4) F18(5.6,4) F19(6.4,4) F20(7.2,4) F21(8,4) G1(-8,3.2) G2(-7.2,3.2) G3(-6.4,3.2) G4(-5.6,3.2) G5(-4.8,3.2) G6(-4,3.2) G7(-3.2,3.2) G8(-2.4,3.2) G9(-1.6,3.2) G10(-0.8,3.2) G11(0,3.2) G12(0.8,3.2) G13(1.6,3.2) G14(2.4,3.2) G15(3.2,3.2) G16(4,3.2) G17(4.8,3.2) G18(5.6,3.2) G19(6.4,3.2) G20(7.2,3.2) G21(8,3.2) H1(-8,2.4) H2(-7.2,2.4) H3(-6.4,2.4) H4(-5.6,2.4) H5(-4.8,2.4) H6(-4,2.4) H7(-3.2,2.4) H8(-2.4,2.4) H9(-1.6,2.4) H10(-0.8,2.4) H11(0,2.4) H12(0.8,2.4) H13(1.6,2.4) H14(2.4,2.4) H15(3.2,2.4) H16(4,2.4) H17(4.8,2.4) H18(5.6,2.4) H19(6.4,2.4) H20(7.2,2.4) H21(8,2.4) J1(-8,1.6) J2(-7.2,1.6) J3(-6.4,1.6) J4(-5.6,1.6) J5(-4.8,1.6) J6(-4,1.6) J7(-3.2,1.6) J8(-2.4,1.6) J9(-1.6,1.6) J10(-0.8,1.6) J11(0,1.6) J12(0.8,1.6) J13(1.6,1.6) J14(2.4,1.6) J15(3.2,1.6) J16(4,1.6) J17(4.8,1.6) J18(5.6,1.6) J19(6.4,1.6) J20(7.2,1.6) J21(8,1.6) K1(-8,0.8) K2(-7.2,0.8) K3(-6.4,0.8) K4(-5.6,0.8) K5(-4.8,0.8) K6(-4,0.8) K7(-3.2,0.8) K8(-2.4,0.8) K9(-1.6,0.8) K10(-0.8,0.8) K11(0,0.8) K12(0.8,0.8) K13(1.6,0.8) K14(2.4,0.8) K15(3.2,0.8) K16(4,0.8) K17(4.8,0.8) K18(5.6,0.8) K19(6.4,0.8) K20(7.2,0.8) K21(8,0.8) L1(-8,0) L2(-7.2,0) L3(-6.4,0) L4(-5.6,0) L5(-4.8,0) L6(-4,0) L7(-3.2,0) L8(-2.4,0) L9(-1.6,0) L10(-0.8,0) L11(0,0) L12(0.8,0) L13(1.6,0) L14(2.4,0) L15(3.2,0) L16(4,0) L17(4.8,0) L18(5.6,0) L19(6.4,0) L20(7.2,0) L21(8,0) M1(-8,-0.8) M2(-7.2,-0.8) M3(-6.4,-0.8) M4(-5.6,-0.8) M5(-4.8,-0.8) M6(-4,-0.8) M7(-3.2,-0.8) M8(-2.4,-0.8) M9(-1.6,-0.8) M10(-0.8,-0.8) M11(0,-0.8) M12(0.8,-0.8) M13(1.6,-0.8) M14(2.4,-0.8) M15(3.2,-0.8) M16(4,-0.8) M17(4.8,-0.8) M18(5.6,-0.8) M19(6.4,-0.8) M20(7.2,-0.8) M21(8,-0.8) N1(-8,-1.6) N2(-7.2,-1.6) N3(-6.4,-1.6) N4(-5.6,-1.6) N5(-4.8,-1.6) N6(-4,-1.6) N7(-3.2,-1.6) N8(-2.4,-1.6) N9(-1.6,-1.6) N10(-0.8,-1.6) N11(0,-1.6) N12(0.8,-1.6) N13(1.6,-1.6) N14(2.4,-1.6) N15(3.2,-1.6) N16(4,-1.6) N17(4.8,-1.6) N18(5.6,-1.6) N19(6.4,-1.6) N20(7.2,-1.6) N21(8,-1.6) P1(-8,-2.4) P2(-7.2,-2.4) P3(-6.4,-2.4) P4(-5.6,-2.4) P5(-4.8,-2.4) P6(-4,-2.4) P7(-3.2,-2.4) P8(-2.4,-2.4) P9(-1.6,-2.4) P10(-0.8,-2.4) P11(0,-2.4) P12(0.8,-2.4) P13(1.6,-2.4) P14(2.4,-2.4) P15(3.2,-2.4) P16(4,-2.4) P17(4.8,-2.4) P18(5.6,-2.4) P19(6.4,-2.4) P20(7.2,-2.4) P21(8,-2.4) R1(-8,-3.2) R2(-7.2,-3.2) R3(-6.4,-3.2) R4(-5.6,-3.2) R5(-4.8,-3.2) R6(-4,-3.2) R7(-3.2,-3.2) R8(-2.4,-3.2) R9(-1.6,-3.2) R10(-0.8,-3.2) R11(0,-3.2) R12(0.8,-3.2) R13(1.6,-3.2) R14(2.4,-3.2) R15(3.2,-3.2) R16(4,-3.2) R17(4.8,-3.2) R18(5.6,-3.2) R19(6.4,-3.2) R20(7.2,-3.2) R21(8,-3.2) T1(-8,-4) T2(-7.2,-4) T3(-6.4,-4) T4(-5.6,-4) T5(-4.8,-4) T6(-4,-4) T7(-3.2,-4) T8(-2.4,-4) T9(-1.6,-4) T10(-0.8,-4) T11(0,-4) T12(0.8,-4) T13(1.6,-4) T14(2.4,-4) T15(3.2,-4) T16(4,-4) T17(4.8,-4) T18(5.6,-4) T19(6.4,-4) T20(7.2,-4) T21(8,-4) U1(-8,-4.8) U2(-7.2,-4.8) U3(-6.4,-4.8) U4(-5.6,-4.8) U5(-4.8,-4.8) U6(-4,-4.8) U7(-3.2,-4.8) U8(-2.4,-4.8) U9(-1.6,-4.8) U10(-0.8,-4.8) U11(0,-4.8) U12(0.8,-4.8) U13(1.6,-4.8) U14(2.4,-4.8) U15(3.2,-4.8) U16(4,-4.8) U17(4.8,-4.8) U18(5.6,-4.8) U19(6.4,-4.8) U20(7.2,-4.8) U21(8,-4.8) V1(-8,-5.6) V2(-7.2,-5.6) V3(-6.4,-5.6) V4(-5.6,-5.6) V5(-4.8,-5.6) V6(-4,-5.6) V7(-3.2,-5.6) V8(-2.4,-5.6) V9(-1.6,-5.6) V10(-0.8,-5.6) V11(0,-5.6) V12(0.8,-5.6) V13(1.6,-5.6) V14(2.4,-5.6) V15(3.2,-5.6) V16(4,-5.6) V17(4.8,-5.6) V18(5.6,-5.6) V19(6.4,-5.6) V20(7.2,-5.6) V21(8,-5.6) W1(-8,-6.4) W2(-7.2,-6.4) W3(-6.4,-6.4) W4(-5.6,-6.4) W5(-4.8,-6.4) W6(-4,-6.4) W7(-3.2,-6.4) W8(-2.4,-6.4) W9(-1.6,-6.4) W10(-0.8,-6.4) W11(0,-6.4) W12(0.8,-6.4) W13(1.6,-6.4) W14(2.4,-6.4) W15(3.2,-6.4) W16(4,-6.4) W17(4.8,-6.4) W18(5.6,-6.4) W19(6.4,-6.4) W20(7.2,-6.4) W21(8,-6.4) Y1(-8,-7.2) Y2(-7.2,-7.2) Y3(-6.4,-7.2) Y4(-5.6,-7.2) Y5(-4.8,-7.2) Y6(-4,-7.2) Y7(-3.2,-7.2) Y8(-2.4,-7.2) Y9(-1.6,-7.2) Y10(-0.8,-7.2) Y11(0,-7.2) Y12(0.8,-7.2) Y13(1.6,-7.2) Y14(2.4,-7.2) Y15(3.2,-7.2) Y16(4,-7.2) Y17(4.8,-7.2) Y18(5.6,-7.2) Y19(6.4,-7.2) Y20(7.2,-7.2) Y21(8,-7.2)
HDR_1X2_90120-0122_S_T_5-6
  rect 1.702x1.702 hole 1.016: 1(0,0)
  round 1.702 hole 1.016: 2(-2.54,0)
HDR_2X5_PEC05DAAN_S_T_8-6
  rect 1.702x1.702 hole 1.016: 1(0,0)
  round 1.702 hole 1.016: 2(0,2.54) 3(2.54,0) 4(2.54,2.54) 5(5.08,0) 6(5.08,2.54) 7(7.62,0) 8(7.62,2.54) 9(10.16,0) 10(10.16,2.54)
HDR_2X10_FTR-110-51-D-06_S_S_8-7
  rect 0.711x3.124 smd: 1(-5.715,-2.578) 2(-5.715,2.578) 3(-4.445,-2.578) 4(-4.445,2.578) 5(-3.175,-2.578) 7(-1.905,-2.578) 8(-1.905,2.578) 9(-0.635,-2.578) 10(-0.635,2.578) 11(0.635,-2.578) 12(0.635,2.578) 13(1.905,-2.578) 14(1.905,2.578) 15(3.175,-2.578) 16(3.175,2.578) 17(4.445,-2.578) 18(4.445,2.578) 19(5.715,-2.578) 20(5.715,2.578)
HDR_2X10_PREC010DAAN_S_T_8-4
  rect 1.702x1.702 hole 1.016: 1(0,0)
  round 1.702 hole 1.016: 2(0,2.54) 3(2.54,0) 4(2.54,2.54) 5(5.08,0) 6(5.08,2.54) 7(7.62,0) 8(7.62,2.54) 9(10.16,0) 10(10.16,2.54) 11(12.7,0) 12(12.7,2.54) 13(15.24,0) 14(15.24,2.54) 15(17.78,0) 16(17.78,2.54) 17(20.32,0) 18(20.32,2.54) 19(22.86,0) 20(22.86,2.54)
HDR_2X20_PEC20DAAN_S_T_8-6
  rect 1.702x1.702 hole 1.016: 1(0,0)
  round 1.702 hole 1.016: 2(0,2.54) 3(2.54,0) 4(2.54,2.54) 5(5.08,0) 6(5.08,2.54) 7(7.62,0) 8(7.62,2.54) 9(10.16,0) 10(10.16,2.54) 11(12.7,0) 12(12.7,2.54) 13(15.24,0) 14(15.24,2.54) 15(17.78,0) 16(17.78,2.54) 17(20.32,0) 18(20.32,2.54) 19(22.86,0) 20(22.86,2.54) 21(25.4,0) 22(25.4,2.54) 23(27.94,0) 24(27.94,2.54) 25(30.48,0) 26(30.48,2.54) 27(33.02,0) 28(33.02,2.54) 29(35.56,0) 30(35.56,2.54) 31(38.1,0) 32(38.1,2.54) 33(40.64,0) 34(40.64,2.54) 35(43.18,0) 36(43.18,2.54) 37(45.72,0) 38(45.72,2.54) 39(48.26,0) 40(48.26,2.54)
HDR_14X2_100_S_T
  rect 1.6x1.6 hole 0.914: 1(0,0)
  round 1.6 hole 0.914: 2(0,-2.54) 3(-2.54,0) 4(-2.54,-2.54) 5(-5.08,0) 6(-5.08,-2.54) 7(-7.62,0) 8(-7.62,-2.54) 9(-10.16,0) 10(-10.16,-2.54) 11(-12.7,0) 12(-12.7,-2.54) 13(-15.24,0) 14(-15.24,-2.54) 15(-17.78,0) 16(-17.78,-2.54) 17(-20.32,0) 18(-20.32,-2.54) 19(-22.86,0) 20(-22.86,-2.54) 21(-25.4,0) 22(-25.4,-2.54) 23(-27.94,0) 24(-27.94,-2.54) 25(-30.48,0) 26(-30.48,-2.54) 27(-33.02,0) 28(-33.02,-2.54)
IND4_DLW21H_90X60_SMD_1-4
  rect 0.889x0.356 smd: 1(-0.85,-0.425) 2(0.85,-0.425) 3(0.85,0.425) 4(-0.85,0.425)
IND0603
  rect 0.914x1.016 smd: 1(-0.8,0) 2(0.8,0)
IND0806_1-2
  rect 1.219x1.803 smd: 1(-0.85,0) 2(0.85,0)
IND1008_1-2
  rect 1.194x2.21 smd: 1(-1.1,0) 2(1.1,0)
IND_1277AS-H_130X110_SMD_1-2
  rect 0.762x2.489 smd: 1(-1.225,0) 2(1.225,0)
IND_XAL6060_260X270_SMD_6-1
  rect 1.422x5.512 smd: 1(-2.02,0) 2(2.02,0)
IND_XFL4020_170X170_SMD_2-1
  rect 0.991x3.404 smd: 1(-1.185,0) 2(1.185,0)
LED_150040GS73220_40X20_SMD_0-4
  rect 0.406x0.457 smd: 1(-0.5,0) 2(0.5,0)
LED_150080VS75000_80X50_SMD_0-8
  rect 1.092x1.194 smd: 1(-1.05,0) 2(1.05,0)
LQFP64_19-68_390X390_1-6
  rect 1.499x0.305 smd: 1(-5.7,3.75) 2(-5.7,3.25) 3(-5.7,2.75) 4(-5.7,2.25) 5(-5.7,1.75) 6(-5.7,1.25) 7(-5.7,0.75) 8(-5.7,0.25) 9(-5.7,-0.25) 10(-5.7,-0.75) 11(-5.7,-1.25) 12(-5.7,-1.75) 13(-5.7,-2.25) 14(-5.7,-2.75) 15(-5.7,-3.25) 16(-5.7,-3.75) 33(5.7,-3.75) 34(5.7,-3.25) 35(5.7,-2.75) 36(5.7,-2.25) 37(5.7,-1.75) 38(5.7,-1.25) 39(5.7,-0.75) 40(5.7,-0.25) 41(5.7,0.25) 42(5.7,0.75) 43(5.7,1.25) 44(5.7,1.75) 45(5.7,2.25) 46(5.7,2.75) 47(5.7,3.25) 48(5.7,3.75)
  rect 0.305x1.499 smd: 17(-3.75,-5.7) 18(-3.25,-5.7) 19(-2.75,-5.7) 20(-2.25,-5.7) 21(-1.75,-5.7) 22(-1.25,-5.7) 23(-0.75,-5.7) 24(-0.25,-5.7) 25(0.25,-5.7) 26(0.75,-5.7) 27(1.25,-5.7) 28(1.75,-5.7) 29(2.25,-5.7) 30(2.75,-5.7) 31(3.25,-5.7) 32(3.75,-5.7) 49(3.75,5.7) 50(3.25,5.7) 51(2.75,5.7) 52(2.25,5.7) 53(1.75,5.7) 54(1.25,5.7) 55(0.75,5.7) 56(0.25,5.7) 57(-0.25,5.7) 58(-0.75,5.7) 59(-1.25,5.7) 60(-1.75,5.7) 61(-2.25,5.7) 62(-2.75,5.7) 63(-3.25,5.7) 64(-3.75,5.7)
MSOP8_25-59_125X125_1-1
  rect 1.448x0.457 smd: 1(-2.2,0.975) 2(-2.2,0.325) 3(-2.2,-0.325) 4(-2.2,-0.975) 5(2.2,-0.975) 6(2.2,-0.325) 7(2.2,0.325) 8(2.2,0.975)
OSC4_ECS-327MVATX-2_100X80_SMD_1
  rect 1.092x0.889 smd: 1(-0.9,-0.7) 2(0.9,-0.7) 3(0.9,0.7) 4(-0.9,0.7)
OSC4_ECS-2520MV_100X80_SMD_0-9
  rect 0.889x0.787 smd: 1(-0.925,-0.725) 2(0.925,-0.725) 3(0.925,0.725) 4(-0.925,0.725)
OSC4_KC3225Z_130X100_SMD_0-8
  rect 1.194x0.94 smd: 1(-1.1,-0.875) 2(1.1,-0.875) 3(1.1,0.875) 4(-1.1,0.875)
QFN20_19-68_185X145_1
  rect 0.864x0.279 smd: 1(-2.225,-0.75) 10(2.225,-0.75) 11(2.225,0.75) 20(-2.225,0.75)
  rect 0.279x0.864 smd: 2(-1.75,-1.725) 3(-1.25,-1.725) 4(-0.75,-1.725) 5(-0.25,-1.725) 6(0.25,-1.725) 7(0.75,-1.725) 8(1.25,-1.725) 9(1.75,-1.725) 12(1.75,1.725) 13(1.25,1.725) 14(0.75,1.725) 15(0.25,1.725) 16(-0.25,1.725) 17(-0.75,1.725) 18(-1.25,1.725) 19(-1.75,1.725)
  rect 3.15x2.159 smd: 21(0,0)
QFN24_19-68_220X140_1
  rect 0.838x0.279 smd: 1(-2.725,-0.75) 12(2.725,-0.75) 13(2.725,0.75) 24(-2.725,0.75)
  rect 0.279x0.838 smd: 2(-2.25,-1.725) 3(-1.75,-1.725) 4(-1.25,-1.725) 5(-0.75,-1.725) 6(-0.25,-1.725) 7(0.25,-1.725) 8(0.75,-1.725) 9(1.25,-1.725) 10(1.75,-1.725) 11(2.25,-1.725) 14(2.25,1.725) 15(1.75,1.725) 16(1.25,1.725) 17(0.75,1.725) 18(0.25,1.725) 19(-0.25,1.725) 20(-0.75,1.725) 21(-1.25,1.725) 22(-1.75,1.725) 23(-2.25,1.725)
  custom 0.508x0.508 smd: 25(0,0)
QFN32_19-68_200X200
  rect 0.838x0.305 smd: 1(-2.5,1.75) 2(-2.5,1.25) 3(-2.5,0.75) 4(-2.5,0.25) 5(-2.5,-0.25) 6(-2.5,-0.75) 7(-2.5,-1.25) 8(-2.5,-1.75) 17(2.5,-1.75) 18(2.5,-1.25) 19(2.5,-0.75) 20(2.5,-0.25) 21(2.5,0.25) 22(2.5,0.75) 23(2.5,1.25) 24(2.5,1.75)
  rect 0.305x0.838 smd: 9(-1.75,-2.5) 10(-1.25,-2.5) 11(-0.75,-2.5) 12(-0.25,-2.5) 13(0.25,-2.5) 14(0.75,-2.5) 15(1.25,-2.5) 16(1.75,-2.5) 25(1.75,2.5) 26(1.25,2.5) 27(0.75,2.5) 28(0.25,2.5) 29(-0.25,2.5) 30(-0.75,2.5) 31(-1.25,2.5) 32(-1.75,2.5)
  rect 3.556x3.556 smd: 33(0,0)
QFN32_19-68_200X200_1_EP3-8
  rect 0.787x0.305 smd: 1(-2.5,1.75) 2(-2.5,1.25) 3(-2.5,0.75) 4(-2.5,0.25) 5(-2.5,-0.25) 6(-2.5,-0.75) 7(-2.5,-1.25) 8(-2.5,-1.75) 17(2.5,-1.75) 18(2.5,-1.25) 19(2.5,-0.75) 20(2.5,-0.25) 21(2.5,0.25) 22(2.5,0.75) 23(2.5,1.25) 24(2.5,1.75)
  rect 0.305x0.787 smd: 9(-1.75,-2.5) 10(-1.25,-2.5) 11(-0.75,-2.5) 12(-0.25,-2.5) 13(0.25,-2.5) 14(0.75,-2.5) 15(1.25,-2.5) 16(1.75,-2.5) 25(1.75,2.5) 26(1.25,2.5) 27(0.75,2.5) 28(0.25,2.5) 29(-0.25,2.5) 30(-0.75,2.5) 31(-1.25,2.5) 32(-1.75,2.5)
  rect 3.785x3.785 smd: 33(0,0)
QFN48_19-68_280X280_1
  rect 0.813x0.305 smd: 1(-3.5,2.75) 2(-3.5,2.25) 3(-3.5,1.75) 4(-3.5,1.25) 5(-3.5,0.75) 6(-3.5,0.25) 7(-3.5,-0.25) 8(-3.5,-0.75) 9(-3.5,-1.25) 10(-3.5,-1.75) 11(-3.5,-2.25) 12(-3.5,-2.75) 25(3.5,-2.75) 26(3.5,-2.25) 27(3.5,-1.75) 28(3.5,-1.25) 29(3.5,-0.75) 30(3.5,-0.25) 31(3.5,0.25) 32(3.5,0.75) 33(3.5,1.25) 34(3.5,1.75) 35(3.5,2.25) 36(3.5,2.75)
  rect 0.305x0.813 smd: 13(-2.75,-3.5) 14(-2.25,-3.5) 15(-1.75,-3.5) 16(-1.25,-3.5) 17(-0.75,-3.5) 18(-0.25,-3.5) 19(0.25,-3.5) 20(0.75,-3.5) 21(1.25,-3.5) 22(1.75,-3.5) 23(2.25,-3.5) 24(2.75,-3.5) 37(2.75,3.5) 38(2.25,3.5) 39(1.75,3.5) 40(1.25,3.5) 41(0.75,3.5) 42(0.25,3.5) 43(-0.25,3.5) 44(-0.75,3.5) 45(-1.25,3.5) 46(-1.75,3.5) 47(-2.25,3.5) 48(-2.75,3.5)
  rect 5.639x5.639 smd: 49(0,0)
QFN72_19-68_390X390_0-9
  rect 0.838x0.254 smd: 1(-4.95,4.25) 2(-4.95,3.75) 3(-4.95,3.25) 4(-4.95,2.75) 5(-4.95,2.25) 6(-4.95,1.75) 7(-4.95,1.25) 8(-4.95,0.75) 9(-4.95,0.25) 10(-4.95,-0.25) 11(-4.95,-0.75) 12(-4.95,-1.25) 13(-4.95,-1.75) 14(-4.95,-2.25) 15(-4.95,-2.75) 16(-4.95,-3.25) 17(-4.95,-3.75) 18(-4.95,-4.25) 37(4.95,-4.25) 38(4.95,-3.75) 39(4.95,-3.25) 40(4.95,-2.75) 41(4.95,-2.25) 42(4.95,-1.75) 43(4.95,-1.25) 44(4.95,-0.75) 45(4.95,-0.25) 46(4.95,0.25) 47(4.95,0.75) 48(4.95,1.25) 49(4.95,1.75) 50(4.95,2.25) 51(4.95,2.75) 52(4.95,3.25) 53(4.95,3.75) 54(4.95,4.25)
  rect 0.254x0.838 smd: 19(-4.25,-4.95) 20(-3.75,-4.95) 21(-3.25,-4.95) 22(-2.75,-4.95) 23(-2.25,-4.95) 24(-1.75,-4.95) 25(-1.25,-4.95) 26(-0.75,-4.95) 27(-0.25,-4.95) 28(0.25,-4.95) 29(0.75,-4.95) 30(1.25,-4.95) 31(1.75,-4.95) 32(2.25,-4.95) 33(2.75,-4.95) 34(3.25,-4.95) 35(3.75,-4.95) 36(4.25,-4.95) 55(4.25,4.95) 56(3.75,4.95) 57(3.25,4.95) 58(2.75,4.95) 59(2.25,4.95) 60(1.75,4.95) 61(1.25,4.95) 62(0.75,4.95) 63(0.25,4.95) 64(-0.25,4.95) 65(-0.75,4.95) 66(-1.25,4.95) 67(-1.75,4.95) 68(-2.25,4.95) 69(-2.75,4.95) 70(-3.25,4.95) 71(-3.75,4.95) 72(-4.25,4.95)
  rect 4.851x4.851 smd: 73(0,0)
RES0201_0-5
  rect 0.356x0.33 smd: 1(-0.28,0) 2(0.28,0)
RES0402_0-5
  rect 0.559x0.635 smd: 1(-0.49,0) 2(0.49,0)
RES0603_0-75
  rect 0.635x0.991 smd: 1(-0.74,0) 2(0.74,0)
RES0805_0-75
  rect 1.194x1.448 smd: 1(-0.95,0) 2(0.95,0)
RES_KRL3216T4_1206-4_0-7
  rect 1.143x0.356 smd: 1(-0.775,1.5) 4(0.775,1.5)
  rect 1.143x2.692 smd: 2(-0.775,-0.325) 3(0.775,-0.325)
RESA_EXB_0201-4_0-5
  rect 0.203x0.305 smd: 1(-0.6,-0.275) 2(-0.2,-0.275) 3(0.2,-0.275) 4(0.6,-0.275) 5(0.6,0.275) 6(0.2,0.275) 7(-0.2,0.275) 8(-0.6,0.275)
SC70-5_1-1
  rect 0.94x0.406 smd: 1(-1.1,0.65) 2(-1.1,0) 3(-1.1,-0.65) 4(1.1,-0.65) 5(1.1,0.65)
SOIC8_1-8
  rect 1.549x0.61 smd: 1(-2.7,1.905) 2(-2.7,0.635) 3(-2.7,-0.635) 4(-2.7,-1.905) 5(2.7,-1.905) 6(2.7,-0.635) 7(2.7,0.635) 8(2.7,1.905)
SON6_19-68_40X60_PB_0-6
  rect 0.356x0.305 smd: 1(-0.3,0.5) 2(-0.3,0) 3(-0.3,-0.5) 4(0.3,-0.5) 5(0.3,0) 6(0.3,0.5)
SON6_25-59_85X85
  rect 0.61x0.356 smd: 1(-1.05,0.65) 2(-1.05,0) 3(-1.05,-0.65) 4(1.05,-0.65) 5(1.05,0) 6(1.05,0.65)
  rect 1.092x1.702 smd: 7(0,0)
SON6_25-59_85X85_0-8
  rect 0.61x0.356 smd: 1(-1.05,0.65) 2(-1.05,0) 3(-1.05,-0.65) 4(1.05,-0.65) 5(1.05,0) 6(1.05,0.65)
  rect 1.067x1.702 smd: 7(0,0)
SON6_CSD17313Q2_80X80
  rect 0.406x0.457 smd: 1(-0.65,-0.923) 2(0,-0.923) 3(0.65,-0.923) 4(0.65,0.923) 5(0,0.923) 6(-0.65,0.923)
  rect 0.406x0.864 smd: 7(0.65,0.096)
  rect 1.041x1.092 smd: 8(-0.325,0)
